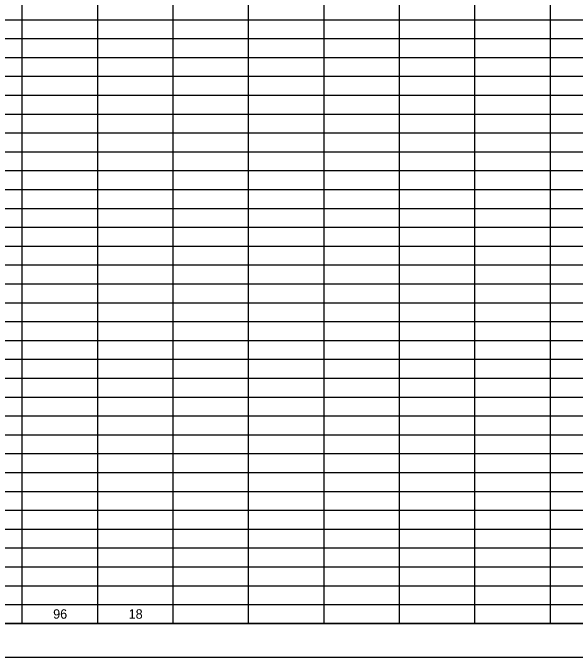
# Model space of a CAD drawing. Extents: x 0 to 34, y 0 to 22.
# Drawn here: x 17.31 to 25.65, y 0 to 9.56 of the extents above; entities that cross this region are included whole.
import ezdxf

# ---------------------------------------------------------------- set-up
doc = ezdxf.new("R2010")
doc.units = 0
for name, color, linetype in [('Default', 7, 'Continuous'), ('SH_Border', 7, 'Continuous'), ('SH_Cut_Line', 7, 'Continuous'), ('SH_Data', 7, 'Continuous')]:
    doc.layers.add(name, color=color, linetype=linetype)

msp = doc.modelspace()

# ---------------------------------------------------------------- linework, layer by layer
at = {"layer": 'SH_Border'}
msp.add_lwpolyline([(1.5, 21.5), (33.5, 21.5), (33.5, 0.5), (1.5, 0.5)], close=True, dxfattribs=at)
at = {"layer": 'SH_Cut_Line'}
msp.add_lwpolyline([(0, 0), (34, 0), (34, 22), (0, 22)], close=True, dxfattribs=at)
at = {"layer": 'SH_Data'}
for p, q in [((17.4435, 21.5), (17.4435, 0.5)), ((18.5635, 21.5), (18.5635, 0.5)), ((19.6835, 21.5), (19.6835, 0.5)), ((20.8035, 21.5), (20.8035, 0.5)), ((21.9235, 21.5), (21.9235, 0.5)), ((23.0435, 21.5), (23.0435, 0.5)), ((24.1635, 21.5), (24.1635, 0.5)), ((25.2835, 21.5), (25.2835, 0.5)), ((1.5, 9.46), (32.0036, 9.46)), ((1.5, 9.18), (32.0036, 9.18)), ((1.5, 8.9), (32.0036, 8.9)), ((1.5, 8.62), (32.0036, 8.62)), ((1.5, 8.34), (32.0036, 8.34)), ((1.5, 8.06), (32.0036, 8.06)), ((1.5, 7.78), (32.0036, 7.78)), ((1.5, 7.5), (32.0036, 7.5)), ((1.5, 7.22), (32.0036, 7.22)), ((1.5, 6.94), (32.0036, 6.94)), ((1.5, 6.66), (32.0036, 6.66)), ((1.5, 6.38), (32.0036, 6.38)), ((1.5, 6.1), (32.0036, 6.1)), ((1.5, 5.82), (32.0036, 5.82)), ((1.5, 5.54), (32.0036, 5.54)), ((1.5, 5.26), (32.0036, 5.26)), ((1.5, 4.98), (32.0036, 4.98)), ((1.5, 4.7), (32.0036, 4.7)), ((1.5, 4.42), (32.0036, 4.42)), ((1.5, 4.14), (32.0036, 4.14)), ((1.5, 3.86), (32.0036, 3.86)), ((1.5, 3.58), (32.0036, 3.58)), ((1.5, 3.3), (32.0036, 3.3)), ((1.5, 3.02), (32.0036, 3.02)), ((1.5, 2.74), (32.0036, 2.74)), ((1.5, 2.46), (32.0036, 2.46)), ((1.5, 2.18), (32.0036, 2.18)), ((1.5, 1.9), (32.0036, 1.9)), ((1.5, 1.62), (32.0036, 1.62)), ((1.5, 1.34), (32.0036, 1.34)), ((1.5, 1.06), (32.0036, 1.06)), ((1.5, 0.78), (32.0036, 0.78)), ((1.5, 0.5), (32.0036, 0.5))]:
    msp.add_line(p, q, dxfattribs=at)

# ---------------------------------------------------------------- texts
at = {"layer": 'Default'}
for s, p in [('96', (17.9069, 0.57)), ('18', (19.0271, 0.57))]:
    msp.add_text(s, height=0.14, dxfattribs=at).set_placement(p)

doc.saveas('drawing.dxf')
